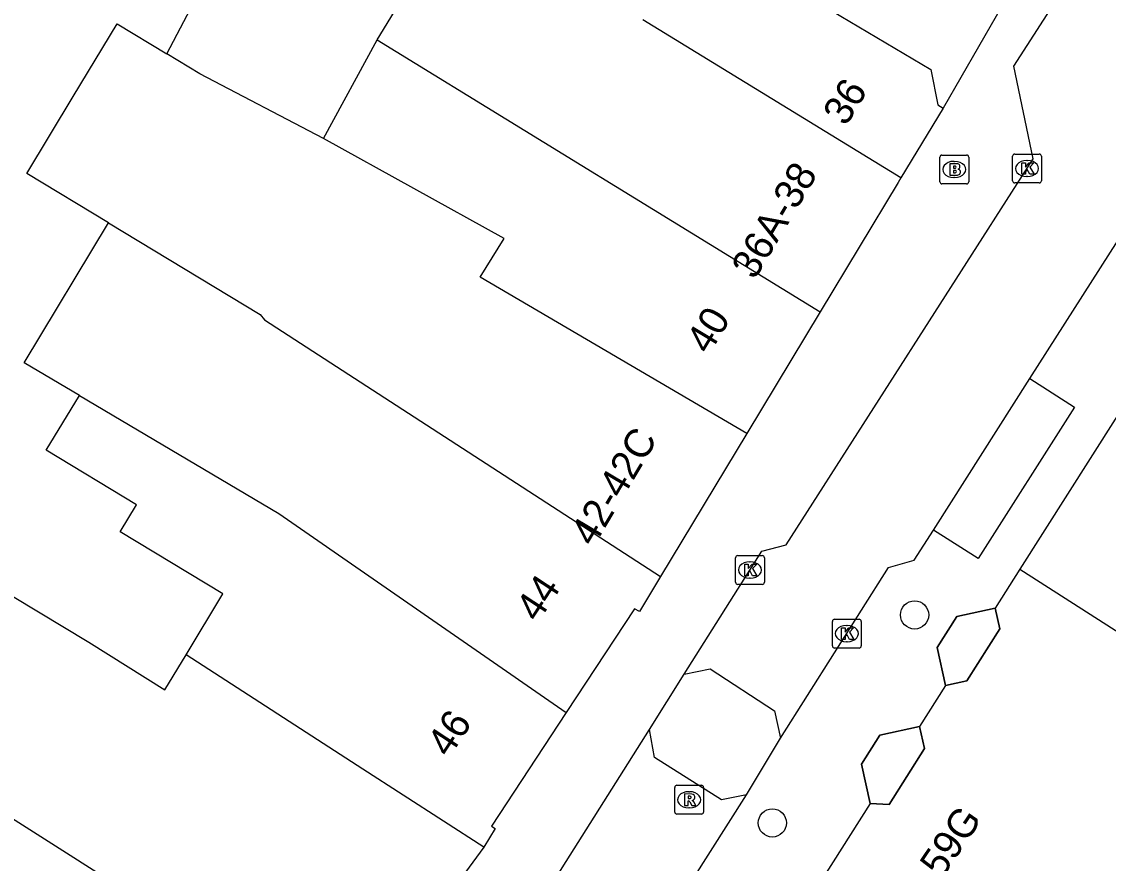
# Model space of a CAD drawing. Extents: x 160664 to 161506, y 382245 to 383288.
# Drawn here: x 161061.79 to 161099.5, y 383037.39 to 383066.59 of the extents above; entities that cross this region are included whole.
import ezdxf

# ---------------------------------------------------------------- set-up
doc = ezdxf.new("R2010")
doc.units = 0
for name, color, linetype in [('IMGEO_Boom', 7, 'Continuous'), ('IMGEO_Brandkraan', 7, 'Continuous'), ('IMGEO_Kolk', 7, 'Continuous'), ('IMGEO_Pand', 7, 'Continuous'), ('IMGEO_Pand_nummerreeks', 7, 'Continuous'), ('IMGEO_Pand_overbouw', 7, 'Continuous'), ('IMGEO_Parkeervlak_open', 7, 'Continuous'), ('IMGEO_Rioolput', 7, 'Continuous'), ('IMGEO_Voetpad_open', 7, 'Continuous'), ('IMGEO_Woonerf_open', 7, 'Continuous')]:
    doc.layers.add(name, color=color, linetype=linetype)

msp = doc.modelspace()

# ---------------------------------------------------------------- linework, layer by layer
at = {"layer": 'IMGEO_Boom'}
for centre in [(161092.783, 383046.006), (161087.845, 383038.791)]:
    msp.add_circle(centre, 0.489, dxfattribs=at)
at = {"layer": 'IMGEO_Brandkraan'}
for p, q in [((161093.658, 383061.035), (161093.658, 383061.887)), ((161093.733, 383061.961), (161094.585, 383061.961)), ((161094.146, 383061.741), (161094.171, 383061.741)), ((161094.659, 383061.887), (161094.659, 383061.035)), ((161094.585, 383060.961), (161093.733, 383060.961)), ((161094.169, 383061.181), (161094.144, 383061.181))]:
    msp.add_line(p, q, dxfattribs=at)
for points in [[(161093.658, 383061.035), (161093.658, 383061.887)], [(161093.733, 383061.961), (161094.585, 383061.961)], [(161094.006, 383061.661), (161094.006, 383061.261), (161094.219, 383061.261)], [(161094.237, 383061.661), (161094.006, 383061.661)], [(161094.659, 383061.887), (161094.659, 383061.035)], [(161094.185, 383061.58), (161094.131, 383061.58), (161094.131, 383061.504)], [(161094.131, 383061.504), (161094.184, 383061.504)], [(161094.193, 383061.428), (161094.131, 383061.428), (161094.131, 383061.347)], [(161094.131, 383061.347), (161094.193, 383061.347)], [(161094.585, 383060.961), (161093.733, 383060.961)]]:
    msp.add_lwpolyline(points, dxfattribs=at)
for centre, radius, start, end in [((161093.735, 383061.885), 0.0765, 91.552, 178.448), ((161093.735, 383061.885), 0.0765, 91.552, 178.448), ((161094.241, 383061.516), 0.145, 59.4692, 91.5367), ((161094.266, 383061.563), 0.0922, 285.5137, 58.1501), ((161094.583, 383061.885), 0.0765, 1.552, 88.448), ((161094.583, 383061.885), 0.0765, 1.552, 88.448), ((161094.186, 383061.542), 0.0379, 267.8285, 90.9355), ((161094.194, 383061.387), 0.0404, 269.8759, 90.5077), ((161094.225, 383061.512), 0.251, 268.6676, 293.5347), ((161094.271, 383061.371), 0.105, 301.3115, 78.989), ((161093.735, 383061.037), 0.0765, 181.552, 268.448), ((161093.735, 383061.037), 0.0765, 181.552, 268.448), ((161094.583, 383061.037), 0.0765, 271.552, 358.448), ((161094.583, 383061.037), 0.0765, 271.552, 358.448)]:
    msp.add_arc(centre, radius, start, end, dxfattribs=at)
for centre, major_axis, ratio, start_param, end_param in [((161094.145, 383061.461), (-0.387, 0.002), 0.722429, 4.712389, 7.853982), ((161094.17, 383061.461), (-0.39, 0.002), 0.717154, 1.570796, 4.712389)]:
    msp.add_ellipse(centre, major_axis=major_axis, ratio=ratio, start_param=start_param, end_param=end_param, dxfattribs=at)
at = {"layer": 'IMGEO_Kolk'}
for p, q in [((161096.184, 383061.069), (161096.184, 383061.921)), ((161096.259, 383061.995), (161097.111, 383061.995)), ((161096.672, 383061.775), (161096.697, 383061.775)), ((161097.185, 383061.921), (161097.185, 383061.069)), ((161097.111, 383060.995), (161096.259, 383060.995)), ((161096.695, 383061.215), (161096.67, 383061.215)), ((161086.642, 383048.066), (161087.494, 383048.066)), ((161086.567, 383047.14), (161086.567, 383047.992)), ((161087.055, 383047.846), (161087.08, 383047.846)), ((161087.568, 383047.992), (161087.568, 383047.14)), ((161087.494, 383047.066), (161086.642, 383047.066)), ((161087.078, 383047.286), (161087.053, 383047.286)), ((161089.929, 383044.932), (161089.929, 383045.784)), ((161090.004, 383045.858), (161090.856, 383045.858)), ((161090.93, 383045.784), (161090.93, 383044.932)), ((161090.417, 383045.638), (161090.442, 383045.638)), ((161090.44, 383045.078), (161090.415, 383045.078)), ((161090.856, 383044.858), (161090.004, 383044.858))]:
    msp.add_line(p, q, dxfattribs=at)
for points in [[(161096.184, 383061.069), (161096.184, 383061.921)], [(161096.259, 383061.995), (161097.111, 383061.995)], [(161096.505, 383061.695), (161096.628, 383061.695), (161096.628, 383061.544), (161096.758, 383061.695), (161096.922, 383061.695), (161096.776, 383061.544), (161096.929, 383061.295), (161096.777, 383061.295), (161096.692, 383061.459), (161096.628, 383061.392), (161096.628, 383061.295), (161096.505, 383061.295), (161096.505, 383061.695)], [(161097.185, 383061.921), (161097.185, 383061.069)], [(161097.111, 383060.995), (161096.259, 383060.995)], [(161086.642, 383048.066), (161087.494, 383048.066)], [(161086.567, 383047.14), (161086.567, 383047.992)], [(161086.888, 383047.766), (161087.011, 383047.766), (161087.011, 383047.615), (161087.141, 383047.766), (161087.305, 383047.766), (161087.159, 383047.615), (161087.312, 383047.366), (161087.16, 383047.366), (161087.075, 383047.53), (161087.011, 383047.463), (161087.011, 383047.366), (161086.888, 383047.366), (161086.888, 383047.766)], [(161087.568, 383047.992), (161087.568, 383047.14)], [(161087.494, 383047.066), (161086.642, 383047.066)], [(161089.929, 383044.932), (161089.929, 383045.784)], [(161090.004, 383045.858), (161090.856, 383045.858)], [(161090.93, 383045.784), (161090.93, 383044.932)], [(161090.25, 383045.558), (161090.373, 383045.558), (161090.373, 383045.407), (161090.503, 383045.558), (161090.667, 383045.558), (161090.521, 383045.407), (161090.674, 383045.158), (161090.522, 383045.158), (161090.437, 383045.322), (161090.373, 383045.255), (161090.373, 383045.158), (161090.25, 383045.158), (161090.25, 383045.558)], [(161090.856, 383044.858), (161090.004, 383044.858)]]:
    msp.add_lwpolyline(points, dxfattribs=at)
for centre, start, end in [((161096.261, 383061.919), 91.552, 178.448), ((161096.261, 383061.919), 91.552, 178.448), ((161097.109, 383061.919), 1.552, 88.448), ((161097.109, 383061.919), 1.552, 88.448), ((161096.261, 383061.071), 181.552, 268.448), ((161096.261, 383061.071), 181.552, 268.448), ((161097.109, 383061.071), 271.552, 358.448), ((161097.109, 383061.071), 271.552, 358.448), ((161086.644, 383047.99), 91.552, 178.448), ((161086.644, 383047.99), 91.552, 178.448), ((161087.492, 383047.99), 1.552, 88.448), ((161087.492, 383047.99), 1.552, 88.448), ((161086.644, 383047.142), 181.552, 268.448), ((161086.644, 383047.142), 181.552, 268.448), ((161087.492, 383047.142), 271.552, 358.448), ((161087.492, 383047.142), 271.552, 358.448), ((161090.006, 383045.782), 91.552, 178.448), ((161090.006, 383045.782), 91.552, 178.448), ((161090.854, 383045.782), 1.552, 88.448), ((161090.854, 383045.782), 1.552, 88.448), ((161090.006, 383044.934), 181.552, 268.448), ((161090.006, 383044.934), 181.552, 268.448), ((161090.854, 383044.934), 271.552, 358.448), ((161090.854, 383044.934), 271.552, 358.448)]:
    msp.add_arc(centre, 0.0765, start, end, dxfattribs=at)
for centre, major_axis, ratio, start_param, end_param in [((161096.671, 383061.495), (-0.387, 0.002), 0.722429, 4.712389, 7.853982), ((161096.696, 383061.495), (-0.39, 0.002), 0.717154, 1.570796, 4.712389), ((161087.054, 383047.566), (-0.387, 0.002), 0.722429, 4.712389, 7.853982), ((161087.079, 383047.566), (-0.39, 0.002), 0.717154, 1.570796, 4.712389), ((161090.416, 383045.358), (-0.387, 0.002), 0.722429, 4.712389, 7.853982), ((161090.441, 383045.358), (-0.39, 0.002), 0.717154, 1.570796, 4.712389)]:
    msp.add_ellipse(centre, major_axis=major_axis, ratio=ratio, start_param=start_param, end_param=end_param, dxfattribs=at)
at = {"layer": 'IMGEO_Pand'}
for points in [[(161074.126, 383065.953), (161076.95, 383070.579)], [(161085.22, 383069.752), (161093.351, 383064.933), (161093.587, 383063.701), (161093.771, 383063.59)], [(161066.831, 383065.474), (161068.604, 383068.854)], [(161092.308, 383061.166), (161083.351, 383066.656)], [(161064.808, 383059.605), (161061.968, 383061.319), (161063.581, 383063.993), (161065.107, 383066.514), (161066.831, 383065.474)], [(161072.272, 383062.537), (161074.126, 383065.953)], [(161074.126, 383065.953), (161089.508, 383056.525)], [(161072.272, 383062.537), (161067.98, 383064.781), (161066.831, 383065.474)], [(161093.771, 383063.59), (161092.308, 383061.166)], [(161086.956, 383052.296), (161077.699, 383057.722), (161078.542, 383059.07), (161072.272, 383062.537)], [(161092.308, 383061.166), (161092.21, 383061.004), (161089.508, 383056.525)], [(161063.794, 383053.623), (161061.88, 383054.754), (161064.808, 383059.605)], [(161064.808, 383059.605), (161070.064, 383056.434), (161070.219, 383056.239), (161083.965, 383047.339)], [(161103.842, 383059.242), (161096.434, 383047.595)], [(161089.508, 383056.525), (161086.956, 383052.296)], [(161067.496, 383044.618), (161068.779, 383046.744), (161065.216, 383048.893), (161065.782, 383049.832), (161062.647, 383051.724), (161063.794, 383053.623)], [(161063.794, 383053.623), (161070.716, 383049.531), (161080.695, 383042.622)], [(161048.444, 383047.224), (161051.939, 383052.395), (161064.119, 383045.068), (161066.763, 383043.403), (161067.496, 383044.618)], [(161086.956, 383052.296), (161083.965, 383047.339)], [(161083.965, 383047.339), (161083.23, 383046.122), (161083.062, 383046.224), (161080.695, 383042.622)], [(161096.434, 383047.595), (161095.575, 383046.244)], [(161096.434, 383047.595), (161121.694, 383031.438)], [(161048.444, 383047.224), (161063.216, 383037.832), (161068.328, 383034.587)], [(161095.575, 383046.244), (161095.736, 383045.52), (161094.591, 383043.72), (161093.857, 383043.556)], [(161077.828, 383037.945), (161073.628, 383040.658), (161067.496, 383044.618)], [(161093.857, 383043.556), (161092.955, 383042.138)], [(161080.695, 383042.622), (161078.102, 383038.676), (161078.225, 383038.602), (161077.828, 383037.945)], [(161092.955, 383042.138), (161093.126, 383041.369), (161091.896, 383039.436), (161091.241, 383039.464)], [(161091.241, 383039.464), (161089.573, 383036.84)], [(161077.828, 383037.945), (161077.074, 383036.911), (161073.387, 383031.365), (161072.765, 383031.735)]]:
    msp.add_lwpolyline(points, dxfattribs=at)
at = {"layer": 'IMGEO_Pand_overbouw'}
for points in [[(161095.575, 383046.244), (161094.243, 383045.948), (161093.563, 383044.877), (161093.857, 383043.556), (161094.591, 383043.72), (161095.736, 383045.52)], [(161092.955, 383042.138), (161091.577, 383041.832), (161090.938, 383040.827), (161091.241, 383039.464), (161091.896, 383039.436), (161093.126, 383041.369)]]:
    msp.add_lwpolyline(points, close=True, dxfattribs=at)
at = {"layer": 'IMGEO_Parkeervlak_open'}
msp.add_lwpolyline([(161093.434, 383048.948), (161096.784, 383054.204)], dxfattribs=at)
at = {"layer": 'IMGEO_Rioolput'}
for p, q in [((161084.458, 383039.17), (161084.458, 383040.022)), ((161084.533, 383040.096), (161085.385, 383040.096)), ((161084.946, 383039.876), (161084.971, 383039.876)), ((161085.459, 383040.022), (161085.459, 383039.17)), ((161085.385, 383039.096), (161084.533, 383039.096)), ((161084.969, 383039.316), (161084.944, 383039.316))]:
    msp.add_line(p, q, dxfattribs=at)
for points in [[(161084.458, 383039.17), (161084.458, 383040.022)], [(161084.533, 383040.096), (161085.385, 383040.096)], [(161085.047, 383039.794), (161084.795, 383039.796), (161084.795, 383039.396)], [(161085.459, 383040.022), (161085.459, 383039.17)], [(161084.795, 383039.396), (161084.919, 383039.396), (161084.919, 383039.558), (161084.93, 383039.558)], [(161084.973, 383039.715), (161084.919, 383039.715), (161084.919, 383039.634)], [(161084.919, 383039.634), (161084.971, 383039.634)], [(161084.977, 383039.529), (161085.048, 383039.396), (161085.188, 383039.396), (161085.123, 383039.522)], [(161085.385, 383039.096), (161084.533, 383039.096)]]:
    msp.add_lwpolyline(points, dxfattribs=at)
for centre, radius, start, end in [((161084.535, 383040.02), 0.0765, 91.552, 178.448), ((161084.535, 383040.02), 0.0765, 91.552, 178.448), ((161085.046, 383039.684), 0.109, 350.3612, 89.416), ((161085.383, 383040.02), 0.0765, 1.552, 88.448), ((161085.383, 383040.02), 0.0765, 1.552, 88.448), ((161084.929, 383039.505), 0.0533, 26.0293, 88.6989), ((161084.955, 383039.823), 0.19, 274.7715, 282.9687), ((161084.979, 383039.619), 0.0964, 77.0061, 93.1865), ((161084.993, 383039.676), 0.0378, 276.6634, 79.6772), ((161085.044, 383039.684), 0.112, 277.5842, 350.9817), ((161085.028, 383039.469), 0.108, 29.5134, 73.7905), ((161084.535, 383039.172), 0.0765, 181.552, 268.448), ((161084.535, 383039.172), 0.0765, 181.552, 268.448), ((161085.383, 383039.172), 0.0765, 271.552, 358.448), ((161085.383, 383039.172), 0.0765, 271.552, 358.448)]:
    msp.add_arc(centre, radius, start, end, dxfattribs=at)
for centre, major_axis, ratio, start_param, end_param in [((161084.945, 383039.596), (-0.387, 0.002), 0.722429, 4.712389, 7.853982), ((161084.97, 383039.596), (-0.39, 0.002), 0.717154, 1.570796, 4.712389)]:
    msp.add_ellipse(centre, major_axis=major_axis, ratio=ratio, start_param=start_param, end_param=end_param, dxfattribs=at)
at = {"layer": 'IMGEO_Voetpad_open'}
for points in [[(161084.789, 383043.953), (161087.48, 383048.216), (161088.319, 383048.44), (161096.899, 383061.826), (161096.232, 383065.041), (161097.948, 383067.723), (161100.236, 383068.269), (161101.27, 383070.058)], [(161096.229, 383067.852), (161093.771, 383063.59)], [(161096.784, 383054.204), (161100.456, 383059.966), (161101.893, 383060.352), (161104.467, 383064.426), (161104.036, 383066.84), (161104.708, 383067.998)], [(161096.784, 383054.204), (161098.334, 383053.216), (161094.984, 383047.96), (161093.434, 383048.948)], [(161088.129, 383041.737), (161091.882, 383047.647), (161092.772, 383047.909), (161093.434, 383048.948)], [(161093.857, 383043.556), (161093.563, 383044.877), (161094.243, 383045.948), (161095.575, 383046.244)], [(161083.578, 383042.034), (161084.789, 383043.953)], [(161071.481, 383022.868), (161083.578, 383042.034)], [(161091.241, 383039.464), (161090.938, 383040.827), (161091.577, 383041.832), (161092.955, 383042.138)], [(161086.946, 383039.769), (161088.129, 383041.737)], [(161074.838, 383020.711), (161086.946, 383039.769)]]:
    msp.add_lwpolyline(points, dxfattribs=at)
at = {"layer": 'IMGEO_Woonerf_open'}
for points in [[(161084.789, 383043.953), (161085.682, 383044.137), (161087.922, 383042.679), (161088.129, 383041.737)], [(161086.946, 383039.769), (161086.077, 383039.594), (161083.75, 383041.057), (161083.578, 383042.034)]]:
    msp.add_lwpolyline(points, dxfattribs=at)

# ---------------------------------------------------------------- texts
at = {"layer": 'IMGEO_Pand_nummerreeks'}
for s, rotation, p in [('36', 58.7455, (161090.401, 383062.929)), ('36A-38', 59.2514, (161087.232, 383057.603)), ('40', 58.8913, (161085.649, 383055.008)), ('42-42C', 59.2381, (161081.637, 383048.336)), ('44', 56.6884, (161079.711, 383045.713)), ('46', 56.69, (161076.63, 383041.024)), ('57-59G', 55.8118, (161092.641, 383035.239))]:
    msp.add_text(s, height=1, rotation=rotation, dxfattribs=at).set_placement(p)

doc.saveas('drawing.dxf')
